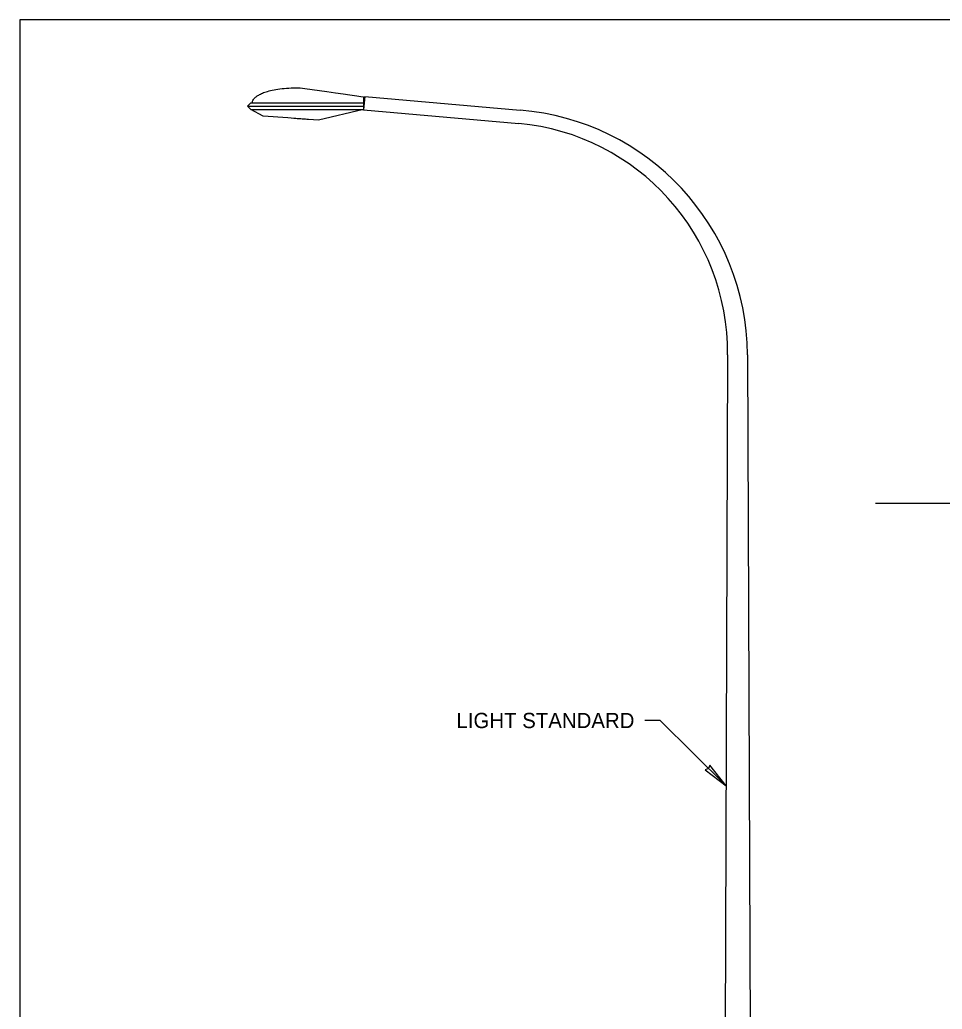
# Model space of a CAD drawing. Extents: x 99862 to 103680, y 99470 to 102076.
# Drawn here: x 99862 to 100829, y 101038 to 102076 of the extents above; entities that cross this region are included whole.
import ezdxf

# ---------------------------------------------------------------- set-up
doc = ezdxf.new("R2010")
doc.units = 0
for name, color, linetype in [('Level 1', 7, 'Continuous'), ('Level 15', 7, 'Continuous'), ('Level 2', 7, 'Continuous'), ('Level 20', 7, 'Continuous'), ('Level 3', 7, 'Continuous')]:
    doc.layers.add(name, color=color, linetype=linetype)

msp = doc.modelspace()

# ---------------------------------------------------------------- linework, layer by layer
at = {"layer": 'Level 1'}
msp.add_lwpolyline([(99862, 99999.5), (103151, 99999.5), (103151, 102075.5), (99862, 102075.5)], close=True, dxfattribs=at)
at = {"layer": 'Level 15'}
for p, q in [((101842.2, 101567.9), (100759.6, 101567.9)), ((100533.6, 101340.4), (100517.6, 101340.4)), ((100533.6, 101340.4), (100602.7, 101271.8))]:
    msp.add_line(p, q, dxfattribs=at)
msp.add_lwpolyline([(100602.7, 101271.8), (100585.9, 101293.5), (100584.3, 101290.1), (100580.9, 101288.5)], close=True, dxfattribs=at)
at = {"layer": 'Level 2'}
for p, q in [((100223.8, 101994.9), (100222.5, 101981)), ((100223.8, 101994.9), (100386.7, 101980.6)), ((100222.5, 101991.4), (100223.5, 101991.4)), ((100222.8, 101984.5), (100222.5, 101984.5)), ((100222.5, 101981), (100385.5, 101966.8)), ((100604.4, 101724.1), (100600.1, 100536.9)), ((100625.3, 101724.1), (100629.6, 100530.4))]:
    msp.add_line(p, q, dxfattribs=at)
for centre, radius, start, end in [((100366, 101722.2), 259.3, 0.42, 85.42), ((100362.5, 101726), 241.9, 359.5498, 84.5498)]:
    msp.add_arc(centre, radius, start, end, dxfattribs=at)
at = {"layer": 'Level 3'}
for p, q in [((100100.7, 101984.9), (100222.5, 101984.9)), ((100104.2, 101988.3), (100105.9, 101988.3)), ((100105.9, 101988.3), (100222.5, 101988.3)), ((100104.2, 101981.4), (100222.5, 101981.4)), ((100117.4, 101974.3), (100104.2, 101981.4)), ((100143, 101972.5), (100117.4, 101974.3)), ((100222.5, 101981.4), (100175.4, 101970.1)), ((100175.4, 101970.1), (100164.9, 101970.9))]:
    msp.add_line(p, q, dxfattribs=at)
for points in [[(100149.9, 102004.1), (100155.9, 102004)], [(100155.9, 102004), (100161.1, 102003.5)], [(100161.1, 102003.5), (100184.1, 102000.2)], [(100184.1, 102000.2), (100193.1, 101998.9)], [(100193.1, 101998.9), (100201.3, 101997.7)], [(100201.3, 101997.7), (100208.3, 101996.7)], [(100208.3, 101996.7), (100215.4, 101995.6)], [(100215.4, 101995.6), (100219.7, 101995)], [(100219.7, 101995), (100222.5, 101994.6)], [(100100.7, 101984.9), (100102.4, 101986.6), (100104.2, 101988.3)], [(100104.2, 101981.4), (100102.4, 101983.2), (100100.7, 101984.9)]]:
    msp.add_lwpolyline(points, dxfattribs=at)
for points, degree in [([(100105.9, 101988.3), (100105.9, 101988.9), (100106.1, 101990), (100106.9, 101991.8), (100108.2, 101993.3), (100110.3, 101995.2), (100113.2, 101997), (100117.5, 101999.1), (100123.2, 102000.9), (100130.3, 102002.5), (100139.2, 102003.7), (100145.7, 102004), (100149.5, 102004.1)], 3), ([(100222.5, 101994.6), (100222.5, 101994.6), (100222.5, 101988.2)], 2), ([(100222.5, 101988.3), (100222.5, 101987.2), (100222.5, 101986), (100222.5, 101984.9)], 2), ([(100222.5, 101984.9), (100222.5, 101983.7), (100222.5, 101982.6), (100222.5, 101981.4)], 2), ([(100164.9, 101970.9), (100162.1, 101971.1), (100159.4, 101971.3), (100156.8, 101971.5), (100153.9, 101971.7), (100148.5, 101972.1), (100143, 101972.5)], 3)]:
    msp.add_open_spline(points, degree=degree, dxfattribs=at)

# ---------------------------------------------------------------- texts
at = {"layer": 'Level 20'}
msp.add_text('LIGHT STANDARD', height=16, dxfattribs=at).set_placement((100320, 101332.4))

doc.saveas('drawing.dxf')
